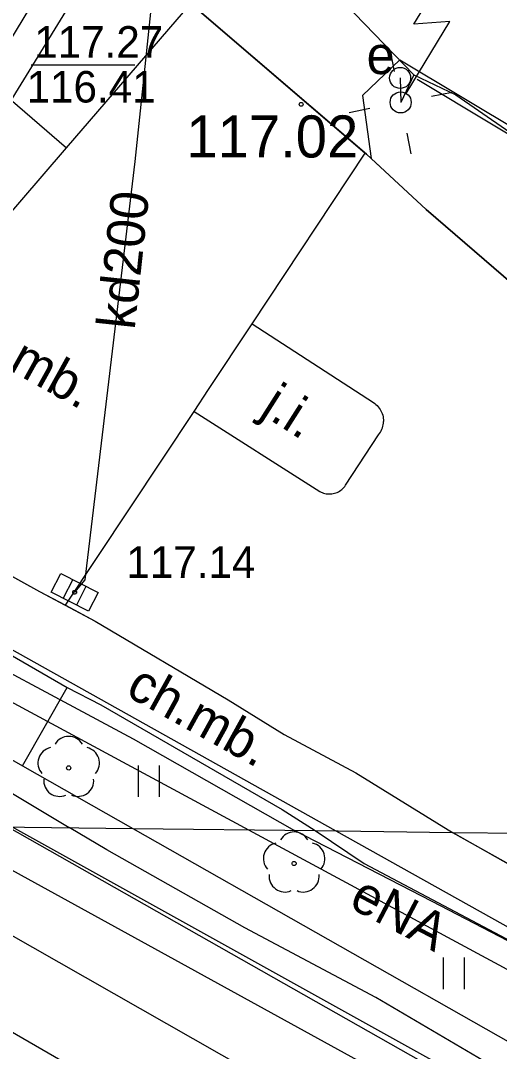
# Model space of a CAD drawing. Extents: x 6434771 to 6436222, y 5663454 to 5664782.
# Drawn here: x 6435099.76 to 6435111.15, y 5663940.88 to 5663965.39 of the extents above; entities that cross this region are included whole.
import ezdxf

# ---------------------------------------------------------------- set-up
doc = ezdxf.new("R2010")
doc.units = 0
for name, color, linetype in [('Warstwa 10', 7, 'Continuous'), ('Warstwa 11', 7, 'Continuous'), ('Warstwa 12', 7, 'Continuous'), ('Warstwa 13', 7, 'Continuous'), ('Warstwa 14', 7, 'Continuous'), ('Warstwa 2', 7, 'Continuous'), ('Warstwa 25', 7, 'Continuous'), ('Warstwa 4', 7, 'Continuous'), ('Warstwa 40', 7, 'Continuous'), ('Warstwa 5', 7, 'Continuous'), ('Warstwa 6', 7, 'Continuous'), ('Warstwa 7', 7, 'Continuous'), ('Warstwa 8', 7, 'Continuous'), ('Warstwa 9', 7, 'Continuous')]:
    doc.layers.add(name, color=color, linetype=linetype)

msp = doc.modelspace()

# ---------------------------------------------------------------- linework, layer by layer
at = {"layer": 'Warstwa 10'}
for points in [[(6435097.639, 5663946.244), (6435110.23, 5663939.33), (6435134.8, 5663925.67), (6435154.54, 5663914.28), (6435171.5, 5663904.82), (6435193.4, 5663892.21), (6435192.998, 5663890.805)], [(6435182.257, 5663838.676), (6435188.304, 5663849.448), (6435193.351, 5663858.439), (6435194.278, 5663859.798), (6435191.577, 5663860.571), (6435190.64, 5663861.662), (6435194.242, 5663871.739), (6435194.776, 5663876.163), (6435192.223, 5663879.254), (6435189.657, 5663881.265), (6435188.718, 5663882.987), (6435189.733, 5663885.054), (6435194.267, 5663892.79), (6435145.165, 5663920.315), (6435099.449, 5663946.22)], [(6435276.336, 5663842.501), (6435260.05, 5663851.86), (6435249.96, 5663857.64), (6435238.71, 5663863.53), (6435238.1, 5663863.95), (6435237.79, 5663864.33), (6435236.77, 5663866.27), (6435229, 5663870.99), (6435224.85, 5663875.36), (6435224.07, 5663876.18), (6435215.14, 5663881.13), (6435208.14, 5663884.9), (6435192.12, 5663893.65), (6435170.67, 5663905.68), (6435152.15, 5663915.89), (6435146.79, 5663915.59), (6435128.02, 5663926.23), (6435125.23, 5663931.72), (6435111.04, 5663939.84), (6435099.552, 5663946.221)], [(6435189.466, 5663896.541), (6435185.427, 5663898.858), (6435180.077, 5663901.858), (6435178.566, 5663902.715), (6435176.008, 5663904.175), (6435171.66, 5663906.62), (6435163.073, 5663911.461), (6435159.126, 5663913.652), (6435147.947, 5663919.891), (6435144.185, 5663921.925), (6435137.94, 5663925.434), (6435134.303, 5663927.559), (6435132.328, 5663928.577), (6435127.254, 5663931.387), (6435124.85, 5663932.815), (6435122.106, 5663934.308), (6435118.714, 5663936.244), (6435111.452, 5663940.261), (6435108.215, 5663942.164), (6435105.1, 5663943.817), (6435101.817, 5663945.674), (6435100.922, 5663946.202)]]:
    msp.add_lwpolyline(points, dxfattribs=at)
at = {"layer": 'Warstwa 11'}
for centre in [(6435100.908, 5663947.623), (6435106.27, 5663945.35)]:
    msp.add_circle(centre, 0.05, dxfattribs=at)
for centre, start, end in [((6435100.908, 5663947.998), 30.1471, 149.8529), ((6435100.551, 5663947.739), 102.1471, 221.8529), ((6435101.265, 5663947.739), 318.1471, 77.8529), ((6435100.688, 5663947.32), 174.1471, 293.8529), ((6435101.128, 5663947.32), 246.1471, 5.8529), ((6435106.27, 5663945.725), 30.1471, 149.8529), ((6435105.913, 5663945.466), 102.1471, 221.8529), ((6435106.627, 5663945.466), 318.1471, 77.8529), ((6435106.05, 5663945.047), 174.1471, 293.8529), ((6435106.49, 5663945.047), 246.1471, 5.8529)]:
    msp.add_arc(centre, 0.375, start, end, dxfattribs=at)
at = {"layer": 'Warstwa 12'}
for points in [[(6435141, 5664096.944), (6435140.712, 5664094.875), (6435140.541, 5664077.81), (6435140.348, 5664058.843), (6435140.244, 5664037.853), (6435131.538, 5664021.545), (6435121.662, 5664002.962), (6435115.163, 5663990.896), (6435113.532, 5663987.769), (6435105.974, 5663975.592), (6435096.975, 5663960.761), (6435093.444, 5663955.018), (6435088.979, 5663947.571), (6435088.964, 5663946.347), (6435089.697, 5663946.338), (6435089.709, 5663947.336), (6435089.904, 5663947.79), (6435099.437, 5663963.329), (6435112.073, 5663983.894), (6435114.868, 5663988.39), (6435124.041, 5664005.528), (6435134.579, 5664025.286), (6435141.037, 5664037.344)], [(6435029.763, 5664005.454), (6435034.388, 5664002.299), (6435042.886, 5663996.481), (6435048.366, 5663992.784), (6435050.056, 5663992.458), (6435053.785, 5663989.318), (6435060.963, 5663983.658), (6435062.158, 5663982.516), (6435067.739, 5663976.436), (6435069.698, 5663972.561), (6435070.863, 5663972.195), (6435071.455, 5663970.037), (6435072.977, 5663964.049), (6435072.957, 5663962.572), (6435082.449, 5663958.039), (6435089.417, 5663954.626), (6435090.354, 5663954.835), (6435092.145, 5663953.831), (6435102.441, 5663948.316), (6435106.279, 5663946.137)], [(6435076.981, 5663977.987), (6435075.009, 5663964.166), (6435107.26, 5663946.125)], [(6435109.543, 5663975.979), (6435105.132, 5663968.235), (6435109.121, 5663964.1), (6435110.12, 5663963.625), (6435119.65, 5663957.044), (6435133.881, 5663947.652), (6435134.322, 5663946.165), (6435134.313, 5663947.375), (6435136.822, 5663945.767)], [(6435062.844, 5663975.005), (6435065.937, 5663971.01), (6435067.536, 5663968.978), (6435072.283, 5663961.757), (6435073.425, 5663961.235), (6435081.75, 5663956.189), (6435083.889, 5663954.89), (6435091.142, 5663951.702), (6435093.466, 5663950.667), (6435100.922, 5663946.202)], [(6435109.121, 5663964.1), (6435108.804, 5663963.447)], [(6435108.791, 5663964.028), (6435108.804, 5663963.447)], [(6435089.227, 5663954.754), (6435105.187, 5663946.15)], [(6435094.917, 5663946.274), (6435142.273, 5663919.31), (6435142.316, 5663919.287), (6435154.155, 5663912.836)], [(6435105.187, 5663946.15), (6435115.17, 5663940.769), (6435143.559, 5663924.775), (6435168.541, 5663910.722), (6435195.023, 5663895.761)], [(6435221.655, 5663880.269), (6435221.936, 5663880.862), (6435218.575, 5663882.674), (6435218.173, 5663882.896), (6435217.302, 5663882.72), (6435214.097, 5663884.591), (6435205.693, 5663889.213), (6435205.45, 5663889.713), (6435204.961, 5663890.309), (6435204.469, 5663890.781), (6435203.051, 5663891.606), (6435201.201, 5663892.622), (6435199.242, 5663893.656), (6435196.622, 5663895.21), (6435191.749, 5663897.878), (6435189.16, 5663899.338), (6435182.205, 5663903.135), (6435181.651, 5663903.483), (6435176.748, 5663906.246), (6435171.243, 5663909.279), (6435113.962, 5663942.157), (6435109.55, 5663944.447), (6435106.279, 5663946.137)], [(6435107.26, 5663946.125), (6435127.986, 5663934.544), (6435149.124, 5663922.599), (6435165.622, 5663913.277), (6435237.784, 5663872.323), (6435252.455, 5663863.225), (6435276.408, 5663848.377)]]:
    msp.add_lwpolyline(points, dxfattribs=at)
at = {"layer": 'Warstwa 14'}
msp.add_line((6435100.013, 5663964.337), (6435102.478, 5663964.337), dxfattribs=at)
at = {"layer": 'Warstwa 2'}
msp.add_lwpolyline([(6435120.241, 5663957.355), (6435109.2, 5663963.993)], dxfattribs=at)
msp.add_circle((6435108.804, 5663963.447), 0.25, dxfattribs=at)
at = {"layer": 'Warstwa 25'}
msp.add_circle((6435106.438, 5663963.401), 0.045, dxfattribs=at)
at = {"layer": 'Warstwa 4'}
for p, q in [((6435101.008, 5663952.1), (6435100.779, 5663951.656)), ((6435101.319, 5663951.94), (6435101.09, 5663951.496))]:
    msp.add_line(p, q, dxfattribs=at)
for points in [[(6435108.657, 5663964.182), (6435108.559, 5663964.673)], [(6435109.539, 5663963.594), (6435110.03, 5663963.692)], [(6435108.069, 5663963.3), (6435107.578, 5663963.202)], [(6435108.951, 5663962.712), (6435109.049, 5663962.221)]]:
    msp.add_lwpolyline(points, dxfattribs=at)
msp.add_lwpolyline([(6435100.719, 5663952.249), (6435101.608, 5663951.791), (6435101.379, 5663951.347), (6435100.49, 5663951.805)], close=True, dxfattribs=at)
msp.add_circle((6435108.791, 5663964.028), 0.25, dxfattribs=at)
at = {"layer": 'Warstwa 40'}
msp.add_line((6435108.934, 5663963.661), (6435109.974, 5663965.369), dxfattribs=at)
msp.add_lwpolyline([(6435108.934, 5663963.661), (6435109.974, 5663965.369), (6435109.116, 5663965.306), (6435110.156, 5663967.014)], dxfattribs=at)
msp.add_circle((6435108.804, 5663963.447), 0.25, dxfattribs=at)
at = {"layer": 'Warstwa 5'}
for p, q in [((6435107.896, 5663963.608), (6435108.786, 5663964.458)), ((6435108.786, 5663964.458), (6435115.518, 5663960.416)), ((6435107.896, 5663963.608), (6435108.105, 5663962.11)), ((6435108.105, 5663962.11), (6435109.413, 5663960.9)), ((6435109.413, 5663960.9), (6435113.491, 5663957.38)), ((6435099.812, 5663947.675), (6435100.875, 5663949.533)), ((6435100.875, 5663949.533), (6435101.674, 5663949.121)), ((6435101.674, 5663949.121), (6435105.986, 5663946.636)), ((6435099.812, 5663947.675), (6435102.437, 5663946.183)), ((6435102.571, 5663946.932), (6435102.571, 5663947.682)), ((6435103.071, 5663946.932), (6435103.071, 5663947.682)), ((6435105.986, 5663946.636), (6435106.769, 5663946.131)), ((6435102.437, 5663946.183), (6435106.769, 5663946.131)), ((6435102.437, 5663946.183), (6435106.769, 5663946.131)), ((6435102.437, 5663946.183), (6435138.996, 5663925.41)), ((6435106.769, 5663946.131), (6435107.932, 5663945.348)), ((6435107.932, 5663945.348), (6435114.748, 5663941.743)), ((6435109.823, 5663942.363), (6435109.823, 5663943.113)), ((6435110.323, 5663942.363), (6435110.323, 5663943.113))]:
    msp.add_line(p, q, dxfattribs=at)
at = {"layer": 'Warstwa 6'}
for points in [[(6435107.989, 5663962.217), (6435103.961, 5663965.662), (6435102.345, 5663967.703), (6435101.696, 5663969.391), (6435101.58, 5663969.96), (6435101.244, 5663971.759), (6435101.206, 5663972.901), (6435101.265, 5663973.917), (6435101.406, 5663974.879), (6435101.672, 5663975.989), (6435101.829, 5663976.486), (6435102.1, 5663977.199), (6435106.404, 5663984.988)], [(6435131.213, 5663945.835), (6435122.972, 5663950.755), (6435117.326, 5663954.474), (6435113.491, 5663957.38), (6435109.413, 5663960.9), (6435107.989, 5663962.217)], [(6435091.847, 5663956.338), (6435093.976, 5663955.277), (6435098.798, 5663952.598), (6435100.211, 5663951.818), (6435101.536, 5663951.115), (6435104.703, 5663949.243), (6435106.032, 5663948.42), (6435107.739, 5663947.509), (6435110.04, 5663946.091)], [(6435197.402, 5663896.978), (6435191.147, 5663900.524), (6435186.751, 5663902.985), (6435183.467, 5663904.85), (6435175.687, 5663909.292), (6435166.852, 5663914.232), (6435158.191, 5663919.121), (6435155.568, 5663920.533), (6435153.709, 5663921.656), (6435152.989, 5663922.003), (6435150.608, 5663923.332), (6435146.497, 5663925.6), (6435141.247, 5663928.558), (6435139.097, 5663929.84), (6435137.384, 5663930.724), (6435135.611, 5663931.733), (6435133.573, 5663932.952), (6435132.233, 5663933.631), (6435124.255, 5663938.11), (6435118.234, 5663941.454), (6435110.04, 5663946.091)]]:
    msp.add_lwpolyline(points, dxfattribs=at)
msp.add_circle((6435101.049, 5663951.798), 0.045, dxfattribs=at)
at = {"layer": 'Warstwa 7'}
msp.add_lwpolyline([(6435107.365, 5663975.955), (6435106.752, 5663974.639), (6435102.838, 5663967.95), (6435103.026, 5663967.253), (6435102.484, 5663962.045), (6435101.292, 5663952.094), (6435101.049, 5663951.798)], dxfattribs=at)
at = {"layer": 'Warstwa 8'}
for p, q in [((6435100.854, 5663962.363), (6435103.834, 5663965.823)), ((6435100.854, 5663962.363), (6435103.834, 5663965.823)), ((6435103.961, 5663965.662), (6435107.961, 5663962.241)), ((6435097.505, 5663965.238), (6435100.854, 5663962.363)), ((6435097.505, 5663965.238), (6435100.854, 5663962.363)), ((6435098.953, 5663960.156), (6435100.854, 5663962.363)), ((6435098.953, 5663960.156), (6435100.854, 5663962.363)), ((6435105.272, 5663958.185), (6435107.961, 5663962.241)), ((6435105.272, 5663958.185), (6435107.961, 5663962.241)), ((6435107.961, 5663962.241), (6435107.989, 5663962.217)), ((6435107.989, 5663962.217), (6435108.105, 5663962.11)), ((6435108.105, 5663962.11), (6435109.413, 5663960.9)), ((6435109.413, 5663960.9), (6435113.491, 5663957.38)), ((6435104.233, 5663956.618), (6435105.272, 5663958.185)), ((6435104.233, 5663956.618), (6435105.272, 5663958.185)), ((6435105.272, 5663958.185), (6435108.154, 5663956.308)), ((6435105.272, 5663958.185), (6435108.154, 5663956.308)), ((6435103.89, 5663956.101), (6435104.233, 5663956.618)), ((6435103.89, 5663956.101), (6435104.233, 5663956.618)), ((6435108.154, 5663956.308), (6435108.186, 5663956.286)), ((6435108.154, 5663956.308), (6435108.186, 5663956.286)), ((6435108.186, 5663956.286), (6435108.215, 5663956.263)), ((6435108.186, 5663956.286), (6435108.215, 5663956.263)), ((6435108.215, 5663956.263), (6435108.243, 5663956.237)), ((6435108.215, 5663956.263), (6435108.243, 5663956.237)), ((6435108.243, 5663956.237), (6435108.269, 5663956.209)), ((6435108.243, 5663956.237), (6435108.269, 5663956.209)), ((6435108.269, 5663956.209), (6435108.293, 5663956.179)), ((6435108.269, 5663956.209), (6435108.293, 5663956.179)), ((6435100.831, 5663951.489), (6435103.89, 5663956.101)), ((6435100.831, 5663951.489), (6435103.89, 5663956.101)), ((6435103.89, 5663956.101), (6435106.881, 5663954.199)), ((6435103.89, 5663956.101), (6435106.881, 5663954.199)), ((6435108.293, 5663956.179), (6435108.314, 5663956.148)), ((6435108.293, 5663956.179), (6435108.314, 5663956.148)), ((6435108.314, 5663956.148), (6435108.333, 5663956.115)), ((6435108.314, 5663956.148), (6435108.333, 5663956.115)), ((6435108.333, 5663956.115), (6435108.35, 5663956.081)), ((6435108.333, 5663956.115), (6435108.35, 5663956.081)), ((6435108.35, 5663956.081), (6435108.364, 5663956.046)), ((6435108.35, 5663956.081), (6435108.364, 5663956.046)), ((6435108.364, 5663956.046), (6435108.376, 5663956.01)), ((6435108.364, 5663956.046), (6435108.376, 5663956.01)), ((6435108.376, 5663956.01), (6435108.385, 5663955.973)), ((6435108.376, 5663956.01), (6435108.385, 5663955.973)), ((6435108.385, 5663955.973), (6435108.391, 5663955.936)), ((6435108.385, 5663955.973), (6435108.391, 5663955.936)), ((6435108.37, 5663955.711), (6435108.38, 5663955.747)), ((6435108.37, 5663955.711), (6435108.38, 5663955.747)), ((6435108.38, 5663955.747), (6435108.388, 5663955.784)), ((6435108.38, 5663955.747), (6435108.388, 5663955.784)), ((6435108.388, 5663955.784), (6435108.393, 5663955.822)), ((6435108.388, 5663955.784), (6435108.393, 5663955.822)), ((6435108.391, 5663955.936), (6435108.394, 5663955.898)), ((6435108.391, 5663955.936), (6435108.394, 5663955.898)), ((6435108.393, 5663955.822), (6435108.395, 5663955.86)), ((6435108.393, 5663955.822), (6435108.395, 5663955.86)), ((6435108.394, 5663955.898), (6435108.395, 5663955.86)), ((6435108.394, 5663955.898), (6435108.395, 5663955.86)), ((6435107.491, 5663954.342), (6435108.28, 5663955.545)), ((6435107.491, 5663954.342), (6435108.28, 5663955.545)), ((6435108.28, 5663955.545), (6435108.303, 5663955.575)), ((6435108.28, 5663955.545), (6435108.303, 5663955.575)), ((6435108.303, 5663955.575), (6435108.324, 5663955.607)), ((6435108.303, 5663955.575), (6435108.324, 5663955.607)), ((6435108.324, 5663955.607), (6435108.342, 5663955.64)), ((6435108.324, 5663955.607), (6435108.342, 5663955.64)), ((6435108.342, 5663955.64), (6435108.357, 5663955.675)), ((6435108.342, 5663955.64), (6435108.357, 5663955.675)), ((6435108.357, 5663955.675), (6435108.37, 5663955.711)), ((6435108.357, 5663955.675), (6435108.37, 5663955.711)), ((6435107.404, 5663954.244), (6435107.429, 5663954.266)), ((6435107.404, 5663954.244), (6435107.429, 5663954.266)), ((6435107.404, 5663954.244), (6435107.429, 5663954.266)), ((6435107.429, 5663954.266), (6435107.451, 5663954.29)), ((6435107.429, 5663954.266), (6435107.451, 5663954.29)), ((6435107.429, 5663954.266), (6435107.451, 5663954.29)), ((6435107.451, 5663954.29), (6435107.472, 5663954.315)), ((6435107.451, 5663954.29), (6435107.472, 5663954.315)), ((6435107.451, 5663954.29), (6435107.472, 5663954.315)), ((6435107.472, 5663954.315), (6435107.491, 5663954.342)), ((6435107.472, 5663954.315), (6435107.491, 5663954.342)), ((6435107.472, 5663954.315), (6435107.491, 5663954.342)), ((6435106.881, 5663954.199), (6435106.91, 5663954.183)), ((6435106.881, 5663954.199), (6435106.91, 5663954.183)), ((6435106.881, 5663954.199), (6435106.91, 5663954.183)), ((6435106.91, 5663954.183), (6435106.94, 5663954.17)), ((6435106.91, 5663954.183), (6435106.94, 5663954.17)), ((6435106.91, 5663954.183), (6435106.94, 5663954.17)), ((6435106.94, 5663954.17), (6435106.971, 5663954.159)), ((6435106.94, 5663954.17), (6435106.971, 5663954.159)), ((6435106.94, 5663954.17), (6435106.971, 5663954.159)), ((6435106.971, 5663954.159), (6435107.003, 5663954.15)), ((6435106.971, 5663954.159), (6435107.003, 5663954.15)), ((6435106.971, 5663954.159), (6435107.003, 5663954.15)), ((6435107.003, 5663954.15), (6435107.035, 5663954.143)), ((6435107.003, 5663954.15), (6435107.035, 5663954.143)), ((6435107.003, 5663954.15), (6435107.035, 5663954.143)), ((6435107.035, 5663954.143), (6435107.068, 5663954.139)), ((6435107.035, 5663954.143), (6435107.068, 5663954.139)), ((6435107.035, 5663954.143), (6435107.068, 5663954.139)), ((6435107.068, 5663954.139), (6435107.101, 5663954.137)), ((6435107.068, 5663954.139), (6435107.101, 5663954.137)), ((6435107.068, 5663954.139), (6435107.101, 5663954.137)), ((6435107.101, 5663954.137), (6435107.134, 5663954.137)), ((6435107.101, 5663954.137), (6435107.134, 5663954.137)), ((6435107.101, 5663954.137), (6435107.134, 5663954.137)), ((6435107.134, 5663954.137), (6435107.166, 5663954.14)), ((6435107.134, 5663954.137), (6435107.166, 5663954.14)), ((6435107.134, 5663954.137), (6435107.166, 5663954.14)), ((6435107.166, 5663954.14), (6435107.199, 5663954.145)), ((6435107.166, 5663954.14), (6435107.199, 5663954.145)), ((6435107.166, 5663954.14), (6435107.199, 5663954.145)), ((6435107.199, 5663954.145), (6435107.231, 5663954.153)), ((6435107.199, 5663954.145), (6435107.231, 5663954.153)), ((6435107.199, 5663954.145), (6435107.231, 5663954.153)), ((6435107.231, 5663954.153), (6435107.262, 5663954.163)), ((6435107.231, 5663954.153), (6435107.262, 5663954.163)), ((6435107.231, 5663954.153), (6435107.262, 5663954.163)), ((6435107.262, 5663954.163), (6435107.293, 5663954.175)), ((6435107.262, 5663954.163), (6435107.293, 5663954.175)), ((6435107.262, 5663954.163), (6435107.293, 5663954.175)), ((6435107.293, 5663954.175), (6435107.323, 5663954.189)), ((6435107.293, 5663954.175), (6435107.323, 5663954.189)), ((6435107.293, 5663954.175), (6435107.323, 5663954.189)), ((6435107.323, 5663954.189), (6435107.351, 5663954.205)), ((6435107.323, 5663954.189), (6435107.351, 5663954.205)), ((6435107.323, 5663954.189), (6435107.351, 5663954.205)), ((6435107.351, 5663954.205), (6435107.378, 5663954.224)), ((6435107.351, 5663954.205), (6435107.378, 5663954.224)), ((6435107.351, 5663954.205), (6435107.378, 5663954.224)), ((6435107.378, 5663954.224), (6435107.404, 5663954.244)), ((6435107.378, 5663954.224), (6435107.404, 5663954.244)), ((6435107.378, 5663954.224), (6435107.404, 5663954.244)), ((6435098.798, 5663952.598), (6435100.211, 5663951.818)), ((6435100.211, 5663951.818), (6435100.831, 5663951.489)), ((6435100.831, 5663951.489), (6435101.536, 5663951.115)), ((6435101.536, 5663951.115), (6435104.703, 5663949.243)), ((6435104.703, 5663949.243), (6435106.032, 5663948.42)), ((6435106.032, 5663948.42), (6435107.739, 5663947.509)), ((6435107.739, 5663947.509), (6435110.04, 5663946.091)), ((6435110.04, 5663946.091), (6435131.213, 5663945.835)), ((6435110.04, 5663946.091), (6435131.213, 5663945.835)), ((6435110.04, 5663946.091), (6435118.234, 5663941.454))]:
    msp.add_line(p, q, dxfattribs=at)
at = {"layer": 'Warstwa 9'}
for p, q in [((6435103.961, 5663965.662), (6435107.961, 5663962.241)), ((6435107.896, 5663963.608), (6435108.786, 5663964.458)), ((6435108.786, 5663964.458), (6435115.518, 5663960.416)), ((6435107.896, 5663963.608), (6435108.105, 5663962.11)), ((6435107.961, 5663962.241), (6435107.989, 5663962.217)), ((6435107.989, 5663962.217), (6435108.105, 5663962.11)), ((6435095.541, 5663952.617), (6435100.875, 5663949.533)), ((6435095.541, 5663952.617), (6435100.875, 5663949.533)), ((6435098.798, 5663952.598), (6435100.211, 5663951.818)), ((6435100.211, 5663951.818), (6435100.831, 5663951.489)), ((6435100.831, 5663951.489), (6435101.536, 5663951.115)), ((6435101.536, 5663951.115), (6435104.703, 5663949.243)), ((6435094.428, 5663950.711), (6435099.812, 5663947.675)), ((6435094.428, 5663950.711), (6435099.812, 5663947.675)), ((6435099.812, 5663947.675), (6435100.875, 5663949.533)), ((6435100.875, 5663949.533), (6435101.674, 5663949.121)), ((6435101.674, 5663949.121), (6435105.986, 5663946.636)), ((6435104.703, 5663949.243), (6435106.032, 5663948.42)), ((6435106.032, 5663948.42), (6435107.739, 5663947.509)), ((6435099.812, 5663947.675), (6435102.437, 5663946.183)), ((6435107.739, 5663947.509), (6435110.04, 5663946.091)), ((6435105.986, 5663946.636), (6435106.769, 5663946.131)), ((6435090.91, 5663946.323), (6435102.437, 5663946.183)), ((6435090.91, 5663946.323), (6435102.437, 5663946.183)), ((6435090.91, 5663946.323), (6435135.707, 5663920.53)), ((6435102.437, 5663946.183), (6435138.996, 5663925.41)), ((6435106.769, 5663946.131), (6435110.04, 5663946.091)), ((6435106.769, 5663946.131), (6435110.04, 5663946.091)), ((6435106.769, 5663946.131), (6435107.932, 5663945.348)), ((6435110.04, 5663946.091), (6435118.234, 5663941.454)), ((6435107.932, 5663945.348), (6435114.748, 5663941.743))]:
    msp.add_line(p, q, dxfattribs=at)

# ---------------------------------------------------------------- texts
at = {"layer": 'Warstwa 13'}
msp.add_text('eNA', height=0.9, rotation=332.3671, dxfattribs=at).set_placement((6435107.539, 5663944.324))
at = {"layer": 'Warstwa 14'}
msp.add_text('116.41', height=0.75, dxfattribs=at).set_placement((6435099.907, 5663963.444))
at = {"layer": 'Warstwa 25'}
msp.add_text('117.02', height=1, dxfattribs=at).set_placement((6435103.706, 5663962.137))
at = {"layer": 'Warstwa 5'}
msp.add_text('e', height=0.9, dxfattribs=at).set_placement((6435107.993, 5663964.121))
at = {"layer": 'Warstwa 6'}
for s, p in [('117.27', (6435100.089, 5663964.51)), ('117.14', (6435102.28, 5663952.142))]:
    msp.add_text(s, height=0.75, dxfattribs=at).set_placement(p)
at = {"layer": 'Warstwa 7'}
msp.add_text('kd200', height=0.9, rotation=83.8581, dxfattribs=at).set_placement((6435102.475, 5663958.026))
at = {"layer": 'Warstwa 8'}
for s, rotation, p in [('j.mb.', 330.9462, (6435098.919, 5663957.398)), ('j.i.', 327.5485, (6435105.439, 5663956.055))]:
    msp.add_text(s, height=0.9, rotation=rotation, dxfattribs=at).set_placement(p)
at = {"layer": 'Warstwa 9'}
msp.add_text('ch.mb.', height=0.9, rotation=331.0837, dxfattribs=at).set_placement((6435102.23, 5663949.361))

doc.saveas('drawing.dxf')
